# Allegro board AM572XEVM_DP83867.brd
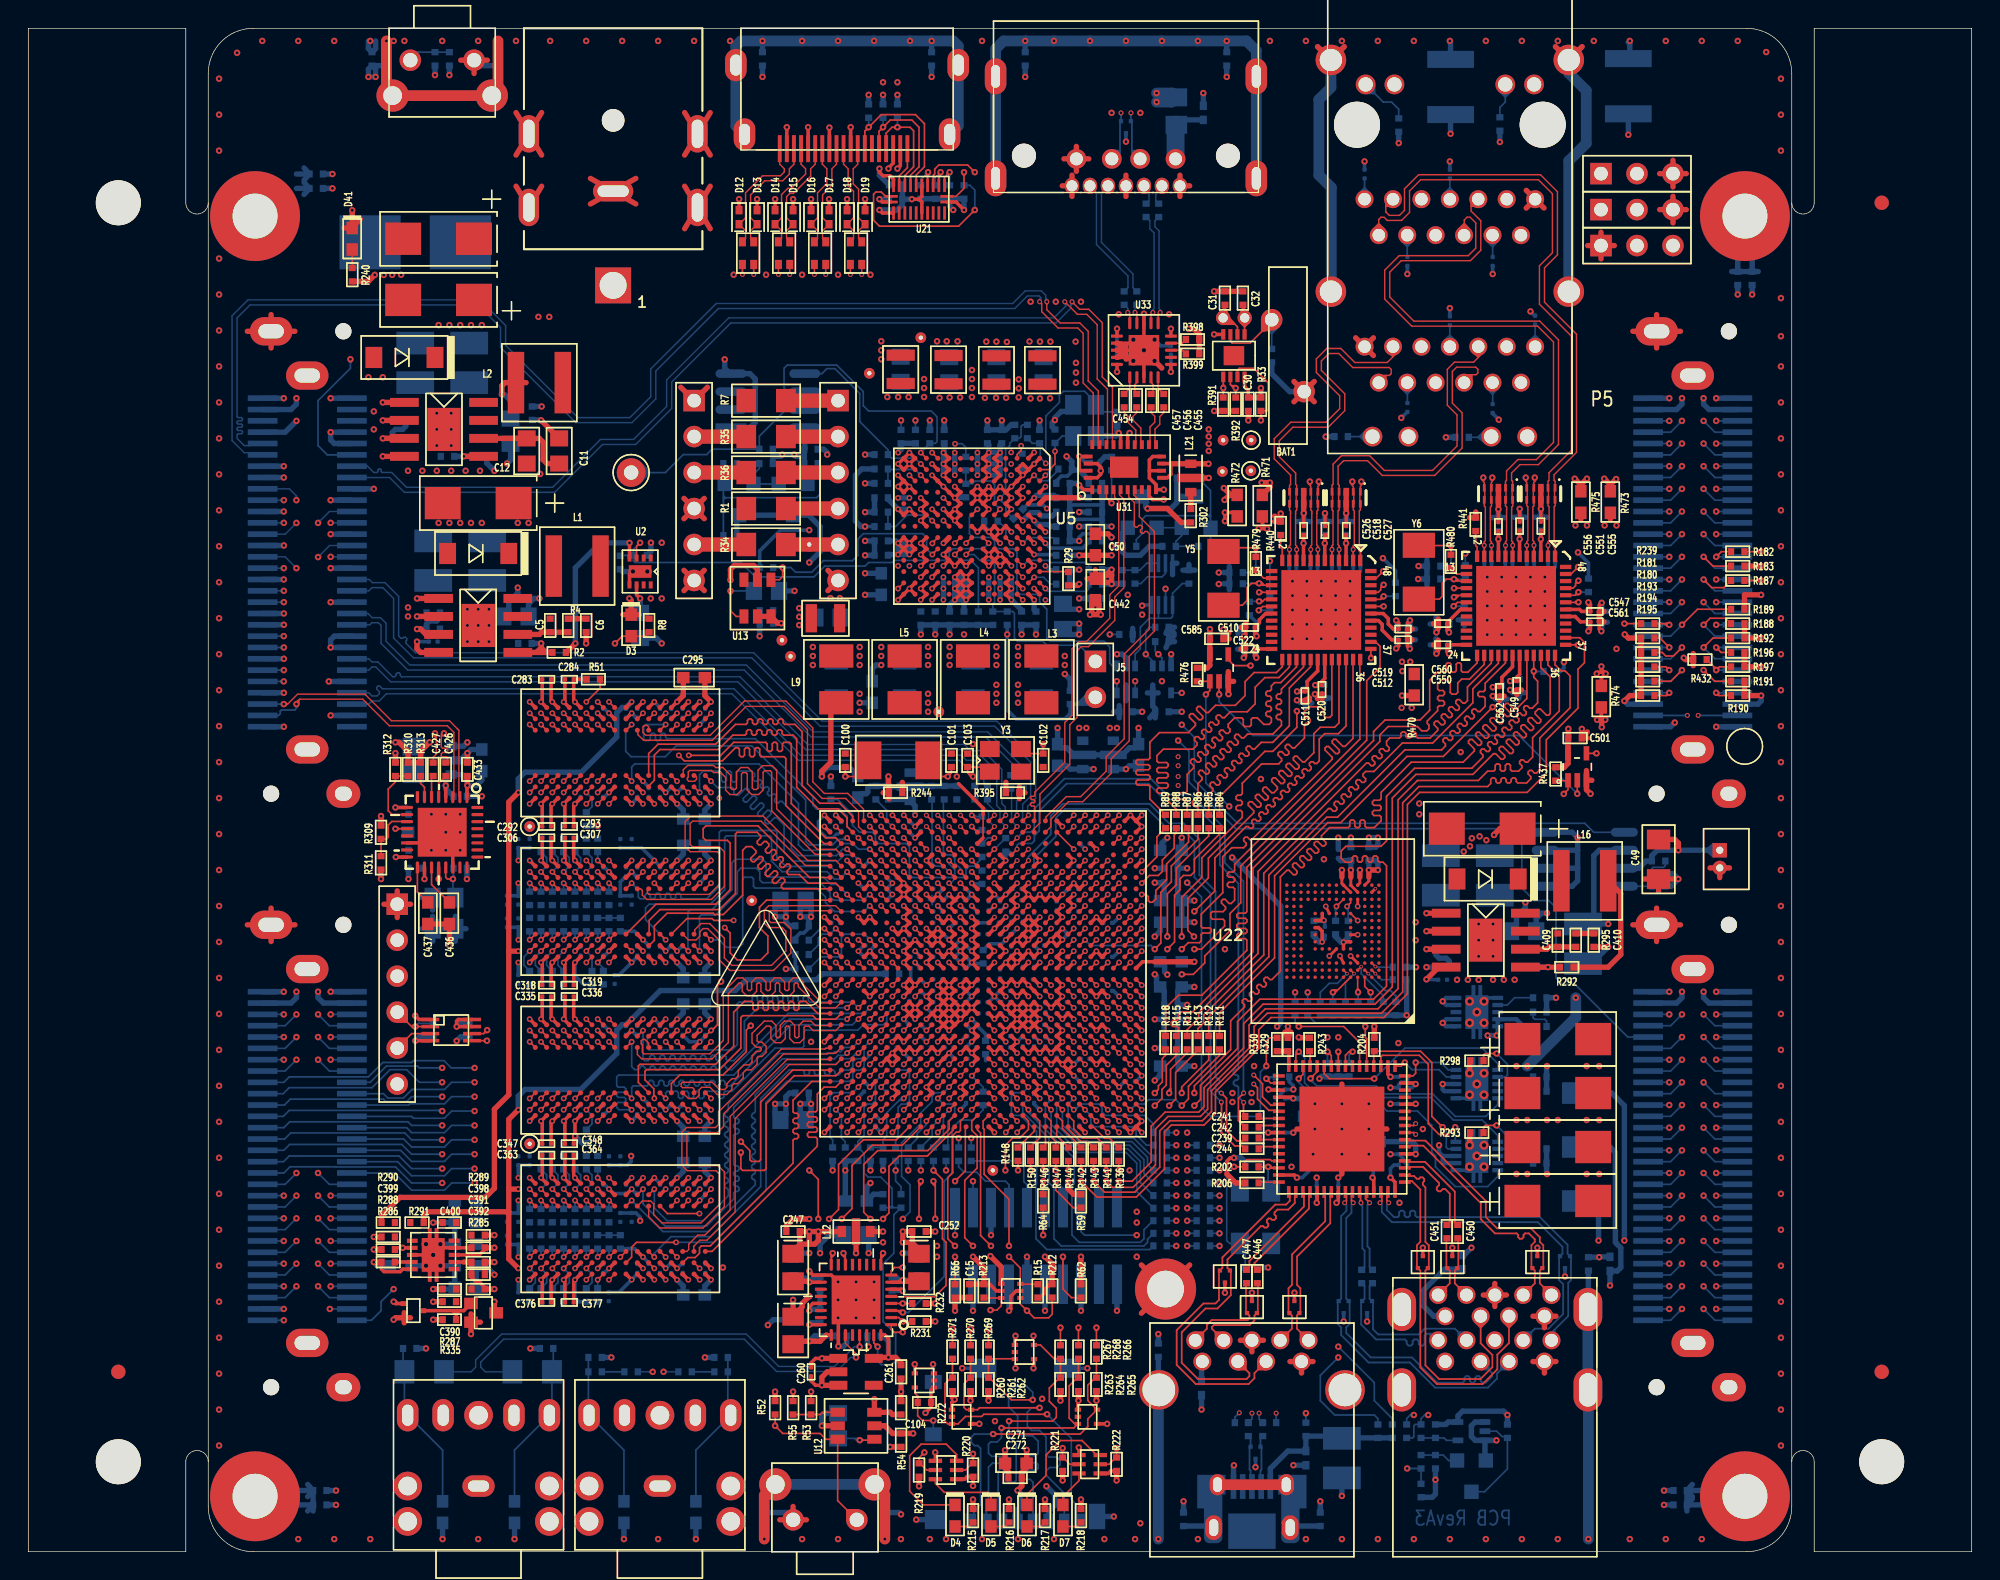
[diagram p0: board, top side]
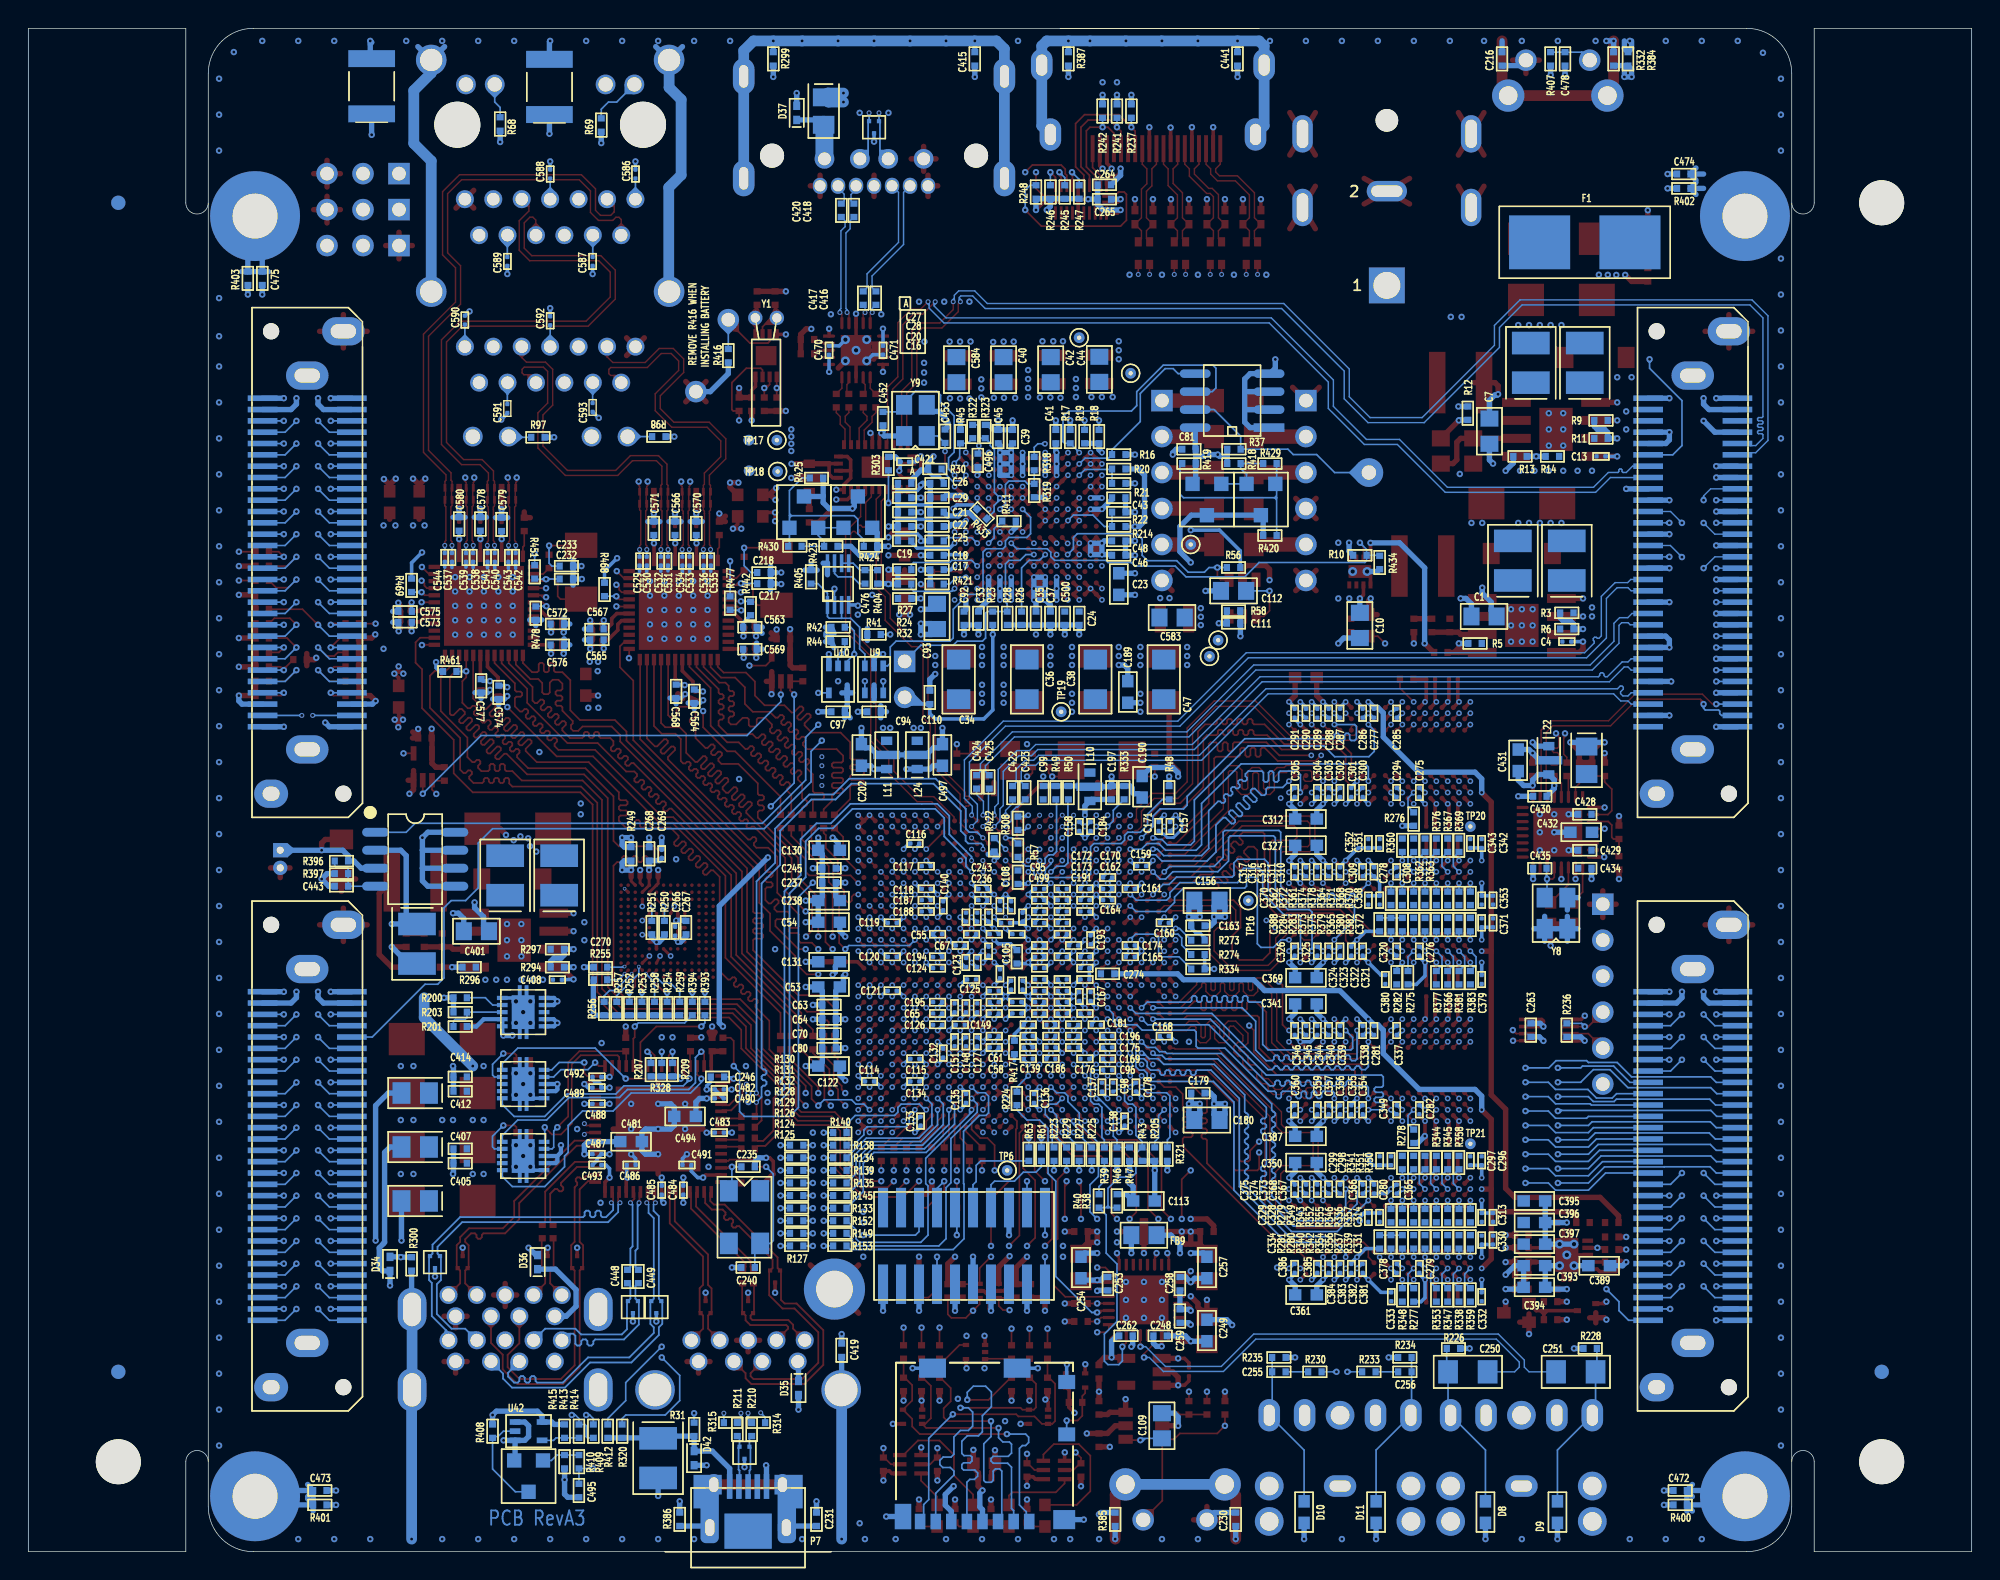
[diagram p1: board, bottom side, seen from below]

Outline 137.16 x 107.57 mm; copper layers: TOP, GND_L2, INT_L3, GND_L4, SIG_L5, PWR_L6, PWR_L7, SIG_L8, GND_L9, SIG_L10, GND_L11, BOTTOM. Coordinates in mm from the lower left corner of the outline.
Outline path: 12.7,6.35 arc(11.91,7.14) 11.11,6.35 11.11,0 0,0 0,107.57 11.11,107.57 11.11,95.25 arc(11.91,94.46) 12.7,95.25 ; 124.46,6.35 arc(125.25,7.14) 126.05,6.35 126.05,0 137.16,0 137.16,107.57 126.05,107.57 126.05,95.25 arc(125.25,94.46) 124.46,95.25 ; 12.7,104.39 12.7,3.17 arc(13.63,0.93) 15.88,0 121.28,0 arc(123.53,0.93) 124.46,3.17 124.46,104.39 arc(123.53,106.64) 121.28,107.57 15.88,107.57 arc(13.63,106.64) 12.7,104.39

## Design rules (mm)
net group AIC_MCLK: nets AIC_MCLK AIC_MCLKR
net group AUDIN: nets AUDIN_L AUDIN_R
net group AUDIO: nets AUDIO_L AUDIO_R
net group CON.PCIE_RX0: nets CON.PCIE_RXN0 CON.PCIE_RXP0
net group CON.PCIE_RX1: nets CON.PCIE_RXN1 CON.PCIE_RXP1
net group CON.PCIE_TXN0: nets CON.PCIE_TXN0 PCIE_TXN0
net group CON.PCIE_TXN1: nets CON.PCIE_TXN1 PCIE_TXN1
net group CON.PCIE_TXP0: nets CON.PCIE_TXP0 PCIE_TXP0
net group CON.PCIE_TXP1: nets CON.PCIE_TXP1 PCIE_TXP1
net group CONN_SATA_RXN: nets CONN_SATA_RXN ESATA_R-
net group CONN_SATA_RXP: nets CONN_SATA_RXP ESATA_R+
net group CONN_SATA_TXN: nets CONN_SATA_TXN ESATA_T-
net group CONN_SATA_TXP: nets CONN_SATA_TXP ESATA_T+
net group CPU_POR_RESETN: nets CPU_POR_RESETN TPS_RST
net group DDR1_DQS0: nets DDR1_DQS0 DDR1_DQSN0
net group DDR1_DQS2: nets DDR1_DQS2 DDR1_DQSN2
net group DDR2_DQS0: nets DDR2_DQS0 DDR2_DQSN0
net group DDR2_DQS2: nets DDR2_DQS2 DDR2_DQSN2
net group DIFFPAIR0: nets GPIO3_23 GPIO3_26
net group DIFFPAIR1: nets GPIO3_16 GPIO3_18
net group DIFFPAIR2: nets GPIO3_8 GPIO3_14
net group DIFFPAIR3: nets GPIO3_7 GPIO3_10
net group DIFFPAIR4: nets GPIO3_20 GPIO3_24
net group DIFFPAIR5: nets GPIO3_11 GPIO3_12
net group DIFFPAIR6: nets GPIO3_9 GPIO3_15
net group DIFFPAIR7: nets GPIO2_31 GPIO3_6
net group EMAC[0]_TXC: nets EMAC[0]_TXC R_EMAC[0]_TXC
net group EMAC[0]_TXCTL: nets EMAC[0]_TXCTL R_EMAC[0]_TXCTL
net group EMAC[0]_TXD0: nets EMAC[0]_TXD0 R_EMAC[0]_TXD0
net group EMAC[0]_TXD1: nets EMAC[0]_TXD1 R_EMAC[0]_TXD1
net group EMAC[0]_TXD2: nets EMAC[0]_TXD2 R_EMAC[0]_TXD2
net group EMAC[0]_TXD3: nets EMAC[0]_TXD3 R_EMAC[0]_TXD3
net group EMAC[1]_TXC: nets EMAC[1]_TXC R_EMAC[1]_TXC
net group EMAC[1]_TXCTL: nets EMAC[1]_TXCTL R_EMAC[1]_TXCTL
net group EMAC[1]_TXD0: nets EMAC[1]_TXD0 R_EMAC[1]_TXD0
net group EMAC[1]_TXD1: nets EMAC[1]_TXD1 R_EMAC[1]_TXD1
net group EMAC[1]_TXD2: nets EMAC[1]_TXD2 R_EMAC[1]_TXD2
net group EMAC[1]_TXD3: nets EMAC[1]_TXD3 R_EMAC[1]_TXD3
net group ETH0_TRD[0]: nets ETH0_TRD[0]N ETH0_TRD[0]P
net group ETH0_TRD[1]: nets ETH0_TRD[1]N ETH0_TRD[1]P
net group ETH0_TRD[2]: nets ETH0_TRD[2]N ETH0_TRD[2]P
net group ETH0_TRD[3]: nets ETH0_TRD[3]N ETH0_TRD[3]P
net group ETH1_TRD[0]: nets ETH1_TRD[0]N ETH1_TRD[0]P
net group ETH1_TRD[1]: nets ETH1_TRD[1]N ETH1_TRD[1]P
net group ETH1_TRD[2]: nets ETH1_TRD[2]N ETH1_TRD[2]P
net group ETH1_TRD[3]: nets ETH1_TRD[3]N ETH1_TRD[3]P
net group EXP_SATA_RX: nets EXP_SATA_RXN EXP_SATA_RXP
net group EXP_SATA_TX: nets EXP_SATA_TXN EXP_SATA_TXP
net group HDMI_TX0: nets HDMI_TX0+ HDMI_TX0-
net group HDMI_TX1: nets HDMI_TX1+ HDMI_TX1-
net group HDMI_TXC: nets HDMI_TXC+ HDMI_TXC-
net group PCI_CONN_REF: nets PCI_CONN_REFN PCI_CONN_REFP
net group PUSB_RXN0: nets PUSB_RXN0 USB_SSTXM0
net group PUSB_RXP0: nets PUSB_RXP0 USB_SSTXP0
net group PUSB_TXN0: nets PUSB_TXN0 USB_SSRXM0
net group PUSB_TXP0: nets PUSB_TXP0 USB_SSRXP0
net group RDRXN: nets RDRXN RXN_MUXC
net group RDRXP: nets RDRXP RXP_MUXC
net group RDTXN: nets RDTXN TXN_MUXC
net group RDTXP: nets RDTXP TXP_MUXC
net group RHDMI_TX0: nets RHDMI_TX0+ RHDMI_TX0-
net group RHDMI_TX1: nets RHDMI_TX1+ RHDMI_TX1-
net group RHDMI_TXC: nets RHDMI_TXC+ RHDMI_TXC-
net group RTCK: nets RTCK RTCKR
net group SAT_RX: nets SAT_RXN SAT_RXP
net group SATA_TX0: nets SAT_TXN SAT_TXP
net group SERDES_CLKN: nets SERDES_CLKN SERDES_IN_REFN
net group SERDES_CLKP: nets SERDES_CLKP SERDES_IN_REFP
net group TCK: nets TCK TCLK
net group TDO: nets TDO TDOR
net group TX1+: nets TX1+ USB_TXP1
net group TX1-: nets TX1- USB_TXM1
net group TX2+: nets TX2+ USB_TXP2
net group TX2-: nets TX2- USB_TXM2
net group TX+: nets TX+ USB_TXP0
net group TX-: nets TX- USB_TXM0
net group USB1_D: nets USB1_DM USB1_DP
net group USB2_D: nets USB2_DM USB2_DP
net group USB2_DEX: nets USB2_DMEX USB2_DPEX
net group USB_D0: nets USB_DM0 USB_DP0
net group USB_D1: nets USB_DM1 USB_DP1
net group USB_D2: nets USB_DM2 USB_DP2
net group USB_D3: nets USB_DM3 USB_DP3
net group USB_RX0: nets USB_RXM0 USB_RXP0
net group USB_RX1: nets USB_RXM1 USB_RXP1
net group USB_RX2: nets USB_RXM2 USB_RXP2
net group USBSP_D: nets USBSP_DM USBSP_DP
net group VBUS_DET: nets N29907779 VBUS_DET
net group VOUT1_CLK: nets VOUT1_CLK VOUT1_RDCLK
net group VOUT1_D0: nets VOUT1_D0 VOUT1_RD0
net group VOUT1_D1: nets VOUT1_D1 VOUT1_RD1
net group VOUT1_D2: nets VOUT1_D2 VOUT1_RD2
net group VOUT1_D3: nets VOUT1_D3 VOUT1_RD3
net group VOUT1_D4: nets VOUT1_D4 VOUT1_RD4
net group VOUT1_D5: nets VOUT1_D5 VOUT1_RD5
net group VOUT1_D6: nets VOUT1_D6 VOUT1_RD6
net group VOUT1_D7: nets VOUT1_D7 VOUT1_RD7
net group VOUT1_D8: nets VOUT1_D8 VOUT1_RD8
net group VOUT1_D9: nets VOUT1_D9 VOUT1_RD9
net group VOUT1_D10: nets VOUT1_D10 VOUT1_RD10
net group VOUT1_D11: nets VOUT1_D11 VOUT1_RD11
net group VOUT1_D12: nets VOUT1_D12 VOUT1_RD12
net group VOUT1_D13: nets VOUT1_D13 VOUT1_RD13
net group VOUT1_D14: nets VOUT1_D14 VOUT1_RD14
net group VOUT1_D15: nets VOUT1_D15 VOUT1_RD15
net group VOUT1_D16: nets VOUT1_D16 VOUT1_RD16
net group VOUT1_D17: nets VOUT1_D17 VOUT1_RD17
net group VOUT1_D18: nets VOUT1_D18 VOUT1_RD18
net group VOUT1_D19: nets VOUT1_D19 VOUT1_RD19
net group VOUT1_D20: nets VOUT1_D20 VOUT1_RD20
net group VOUT1_D21: nets VOUT1_D21 VOUT1_RD21
net group VOUT1_D22: nets VOUT1_D22 VOUT1_RD22
net group VOUT1_D23: nets VOUT1_D23 VOUT1_RD23
net group VOUT1_DE: nets VOUT1_DE VOUT1_RDE
net group VOUT1_HSYNC: nets VOUT1_HSYNC VOUT1_RHSYNC
net group VOUT1_RVSYNC: nets VOUT1_RVSYNC VOUT1_VSYNC
net group DDR1_DQ0: nets DDR1_D0 DDR1_D1 DDR1_D2 DDR1_D3 DDR1_D4 DDR1_D5 DDR1_D6 DDR1_D7 DDR1_DQM0
net group DDR1_DQ1: nets DDR1_D8 DDR1_D9 DDR1_D10 DDR1_D11 DDR1_D12 DDR1_D13 DDR1_D14 DDR1_D15 DDR1_DQM1 DDR1_DQS1 DDR1_DQSN1
net group DDR1_DQ2: nets DDR1_D16 DDR1_D17 DDR1_D18 DDR1_D19 DDR1_D20 DDR1_D21 DDR1_D22 DDR1_D23 DDR1_DQM2
net group DDR1_DQ3: nets DDR1_D24 DDR1_D25 DDR1_D26 DDR1_D27 DDR1_D28 DDR1_D29 DDR1_D30 DDR1_D31 DDR1_DQM3 DDR1_DQS3 DDR1_DQSN3
net group DDR2_DQ0: nets DDR2_D0 DDR2_D1 DDR2_D2 DDR2_D3 DDR2_D4 DDR2_D5 DDR2_D6 DDR2_D7 DDR2_DQM0
net group DDR2_DQ1: nets DDR2_D8 DDR2_D9 DDR2_D10 DDR2_D11 DDR2_D12 DDR2_D13 DDR2_D14 DDR2_D15 DDR2_DQM1 DDR2_DQS1 DDR2_DQSN1
net group DDR2_DQ2: nets DDR2_D16 DDR2_D17 DDR2_D18 DDR2_D19 DDR2_D20 DDR2_D21 DDR2_D22 DDR2_D23 DDR2_DQM2
net group DDR2_DQ3: nets DDR2_D24 DDR2_D25 DDR2_D26 DDR2_D27 DDR2_D28 DDR2_D29 DDR2_D30 DDR2_D31 DDR2_DQM3 DDR2_DQS3 DDR2_DQSN3
net group DDR_VREFSTL1: nets DDR_VREFSTL1 DDR_VREFSTL2 VTT_VOSNS
net group EMAC0_RX: nets EMAC[0]_RXC EMAC[0]_RXCTL EMAC[0]_RXD0 EMAC[0]_RXD1 EMAC[0]_RXD2 EMAC[0]_RXD3
net group EMAC1_RX: nets EMAC[1]_RXC EMAC[1]_RXCTL EMAC[1]_RXD0 EMAC[1]_RXD1 EMAC[1]_RXD2 EMAC[1]_RXD3
net group ENET_PORZ: nets ENET_PORZ PORZ RTC_ISO
net group HDMI: nets HDMI_TX2+ HDMI_TX2- RHDMI_TX2+ RHDMI_TX2-
net group VDAC_3V3: nets AIC_AVDD_DAC3.3 GND_SIGNAL VDAC_3V3
nets with their own width: min track width 0.254; nets ETH0_1V0 ETH0_2V5 ETH0_3V3 ETH1_1V0 ETH1_2V5 ETH1_3V3 LDO_VRTC

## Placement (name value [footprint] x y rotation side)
BAT1  CR1220MFR FV,DNI  [BATT2_78X492]  88.9 84.45 270 top
C1  0.1uf,25V,0805  [805]  34.42 66.04 180 bottom
C2  100uF,10V  [6032]  31.75 74.04 180 top
C3  4.7uF,50V.LESR  [1210]  28.58 69.98 90 bottom
C4  8.2nF,10V,0201  [201]  28.58 64.26 0 bottom
C5  22pF  [402]  36.83 65.41 270 top
C6  .001uF,50V  [402]  39.37 65.41 270 top
C7  0.1uf,25V,0805  [805]  34.04 79.12 270 bottom
C8  100uF,10V  [6032]  28.96 88.39 180 top
C9  100uF,10V  [6032]  28.96 92.71 180 top
C10  220pF,50V  [805]  43.18 65.41 270 bottom
C11  820pF,50V  [805]  37.47 77.72 90 top
C12  15pF,50V  [805]  35.18 77.72 270 top
C13  8.2nF,10V,0201  [201]  26.16 77.34 0 bottom
C14  4.7uF,50V.LESR  [1210]  27.3 83.95 90 bottom
C15  0.1uf,16V  [402]  66.42 18.41 270 top
C16  0.1uf,16V  [402]  75.31 72.39 180 bottom
C17  2.2uF,6.3V  [402]  73.03 69.34 180 bottom
C18  2.2uF,6.3V  [402]  73.03 70.36 180 bottom
C19  2.2uF,6.3V  [402]  75.31 71.37 180 bottom
C20  2.2uF,6.3V  [402]  75.31 73.41 180 bottom
C21  2.2uF,6.3V  [402]  73.03 73.41 180 bottom
C22  2.2uF,6.3V  [402]  73.03 72.39 180 bottom
C23  10uF,6.3V  [603]  60.2 68.33 90 bottom
C24  2.2uF,6.3V  [402]  62.99 65.91 90 bottom
C25  2.2uF,6.3V  [402]  73.03 71.37 180 bottom
C26  2.2uF,6.3V  [402]  73.03 75.44 180 bottom
C27  2.2uF,6.3V  [402]  75.31 75.44 180 bottom
C28  2.2uF,6.3V  [402]  75.31 74.42 180 bottom
C29  2.2uF,6.3V  [402]  73.03 74.42 180 bottom
C30  0.1uf,16V  [402]  86.11 81.03 270 top
C31  10pF,50V  [402]  84.45 88.52 90 top
C32  10pF,50V  [402]  85.72 88.52 90 top
C33  4.7uF,6.3V  [402]  70.1 65.91 270 bottom
C34  47uF,6.3V,1206  [1206]  71.5 61.59 90 bottom
C35  4.7uF,6.3V  [402]  66.04 65.91 270 bottom
C36  47uF,6.3V,1206  [1206]  66.68 61.59 90 bottom
C37  4.7uF,6.3V  [402]  65.02 65.91 270 bottom
C38  47uF,6.3V,1206  [1206]  61.85 61.59 90 bottom
C39  4.7uF,6.3V  [402]  67.69 78.74 90 bottom
C40  47uF,6.3V  [805]  68.33 83.46 270 bottom
C41  4.7uF,6.3V  [402]  64.64 78.74 90 bottom
C42  47uF,6.3V  [805]  65 83.46 270 bottom
C43  4.7uF,6.3V  [402]  60.2 74.42 180 bottom
C44  47uF,6.3V  [805]  61.57 83.49 270 bottom
C45  4.7uF,6.3V  [402]  68.71 78.74 90 bottom
C46  4.7uF,6.3V  [402]  60.2 70.36 180 bottom
C47  47uF,6.3V,1206  [1206]  57.02 61.59 90 bottom
C48  4.7uF,6.3V  [402]  60.2 71.37 180 bottom
C49  47uF,6.3V,1206  [1206]  115.06 48.9 270 top
C50  10uF,6.3V  [603]  75.31 71.12 270 top
C51  0.1uF/201  [201]  70.99 38.4 90 bottom
C52  0.22uF/201  [201]  68.99 38 0 bottom
C53  10uF,6.3V  [603]  80.65 39.88 0 bottom
C54  10uF,6.3V  [603]  80.65 44.45 0 bottom
C55  0.1uF/201  [201]  72.99 43.61 0 bottom
C56  0.22uF/201  [201]  65.79 42.81 180 bottom
C57  0.1uF/201  [201]  68.99 38.8 180 bottom
C58  0.1uF/201  [201]  68.99 35.6 180 bottom
C59  0.1uF/201  [201]  70.19 38.4 90 bottom
C60  0.1uF/201  [201]  70.19 41.61 270 bottom
C61  0.1uF/201  [201]  68.99 36.4 0 bottom
C62  0.1uF/201  [201]  64.19 42.01 180 bottom
C63  2.2uF,6.3V  [402]  80.65 38.61 0 bottom
C64  4.7uF,6.3V  [402]  80.65 37.59 0 bottom
C65  0.47uF/201  [201]  72.99 38 0 bottom
C66  0.1uF/201  [201]  65.79 42.01 180 bottom
C67  0.1uF/201  [201]  71.39 42.81 0 bottom
C68  0.1uF/201  [201]  64.19 43.61 0 bottom
C69  0.1uF/201  [201]  63.39 42.81 180 bottom
C70  4.7uF,6.3V  [402]  80.65 36.58 0 bottom
C71  0.1uF/201  [201]  64.99 36.4 180 bottom
C72  0.1uF/201  [201]  68.59 40.81 270 bottom
C73  0.1uF/201  [201]  70.99 44.81 90 bottom
C74  0.1uF/201  [201]  70.19 44.81 90 bottom
C75  0.1uF/201  [201]  69.39 42.41 270 bottom
C76  0.1uF/201  [201]  67.39 43.61 180 bottom
C77  0.1uF/201  [201]  64.19 39.6 180 bottom
C78  0.22uF/201  [201]  70.59 43.61 180 bottom
C79  0.47uF/201  [201]  68.19 44.41 180 bottom
C80  2.2uF,6.3V  [402]  80.65 35.56 0 bottom
C81  0.1uf,16V  [402]  55.25 77.85 0 bottom
C82  0.1uF/201  [201]  64.19 38.8 180 bottom
C83  0.1uF/201  [201]  64.19 38 180 bottom
C84  0.1uF/201  [201]  64.19 40.41 180 bottom
C85  0.1uF/201  [201]  67.39 38 0 bottom
C86  0.1uF/201  [201]  67.39 38.8 0 bottom
C87  0.1uF/201  [201]  65.79 40.41 0 bottom
C88  0.22uF/201  [201]  65.79 39.6 180 bottom
C89  0.22uF/201  [201]  64.99 37.2 180 bottom
C90  1uF,4V,0201  [201]  65.79 38 0 bottom
C91  1uF,4V,0201  [201]  65.79 38.8 0 bottom
C92  2.2uF,6.3V  [402]  71.12 65.91 90 bottom
C93  22uF,6.3V  [805]  73.03 66.04 270 bottom
C94  0.1uf,16V  [402]  77.47 59.31 0 bottom
C95  0.1uF/201  [201]  65.79 46.81 180 bottom
C96  0.1uF/201  [201]  60.99 34 0 bottom
C97  0.1uf,16V  [402]  80.01 59.31 0 bottom
C98  0.1uF/201  [201]  60.59 32.8 270 bottom
C99  0.1uf,16V  [402]  65.53 53.59 90 bottom
C100  18pF,50V  [402]  57.66 55.88 90 top
C101  18pF,50V  [402]  65.15 55.88 90 top
C102  12pF,50V  [402]  71.63 55.88 270 top
C103  12pF,50V  [402]  66.29 55.88 90 top
C104  0.1uf,16V  [402]  61.59 10.16 90 top
C105  0.1uf,16V  [402]  67.39 42.01 270 bottom
C108  0.1uf,16V  [402]  67.31 47.62 90 bottom
C109  220pF,50V  [805]  57.15 8.89 90 bottom
C110  0.1uf,16V  [402]  73.53 60.33 90 bottom
C111  0.1uf,16V  [402]  52.1 65.56 180 bottom
C112  220pF,50V  [805]  52.1 67.84 0 bottom
C113  10uF,6.3V  [603]  58.42 24.77 180 bottom
C114  0.1uF/201  [201]  77.79 33.2 0 bottom
C115  0.1uF/201  [201]  74.59 34.8 180 bottom
C116  0.1uF/201  [201]  74.59 50.01 180 bottom
C117  0.1uF/201  [201]  73.79 48.41 0 bottom
C118  0.1uF/201  [201]  73.79 46.81 180 bottom
C119  0.1uF/201  [201]  76.19 44.41 0 bottom
C120  0.1uF/201  [201]  76.19 42.01 0 bottom
C121  0.1uF/201  [201]  76.19 39.6 0 bottom
C122  10uF,6.3V  [603]  80.65 34.29 0 bottom
C123  0.1uF/201  [201]  70.99 41.61 90 bottom
C124  0.1uF/201  [201]  72.99 41.21 180 bottom
C125  0.1uF/201  [201]  70.59 40.41 180 bottom
C126  0.1uF/201  [201]  72.99 37.2 0 bottom
C127  0.1uF/201  [201]  70.19 36 90 bottom
C128  0.1uF/201  [201]  66.59 35.6 180 bottom
C129  0.1uF/201  [201]  64.99 35.6 0 bottom
C130  10uF,6.3V  [603]  80.65 49.53 0 bottom
C131  10uF,6.3V  [603]  80.65 41.66 0 bottom
C132  0.1uF/201  [201]  72.59 35.2 270 bottom
C133  0.1uF/201  [201]  74.19 30.4 270 bottom
C134  0.1uF/201  [201]  74.59 33.2 180 bottom
C135  0.1uF/201  [201]  70.99 32 270 bottom
C136  0.1uF/201  [201]  66.19 32 270 bottom
C137  0.1uF/201  [201]  61.39 32.8 90 bottom
C138  0.1uF/201  [201]  59.79 30.4 270 bottom
C139  0.1uF/201  [201]  66.59 34.8 180 bottom
C140  0.1uF/201  [201]  72.59 45.61 90 bottom
C141  1uF,4V,0201  [201]  66.99 44.81 90 bottom
C142  1uF,4V,0201  [201]  62.59 41.21 180 bottom
C143  1uF,4V,0201  [201]  63.39 36.4 180 bottom
C144  1uF,4V,0201  [201]  67.79 45.61 90 bottom
C145  1uF,4V,0201  [201]  62.59 40.41 0 bottom
C146  1uF,4V,0201  [201]  66.59 36.4 0 bottom
C147  1uF,4V,0201  [201]  65.79 45.21 0 bottom
C148  1uF,4V,0201  [201]  70.99 36 270 bottom
C149  1uF,4V,0201  [201]  71.39 37.2 0 bottom
C150  1uF,4V,0201  [201]  62.59 42.01 180 bottom
C151  1uF,4V,0201  [201]  71.79 36 90 bottom
C152  1uF,4V,0201  [201]  68.59 45.61 90 bottom
C153  1uF,4V,0201  [201]  63.39 37.2 180 bottom
C154  1uF,4V,0201  [201]  66.59 37.2 180 bottom
C155  1uF,4V,0201  [201]  71.79 38.4 270 bottom
C156  22uF,6.3V  [805]  53.98 45.97 180 bottom
C157  0.1uF/201  [201]  56.58 51.21 90 bottom
C158  0.1uF/201  [201]  62.99 51.21 90 bottom
C159  0.1uF/201  [201]  58.59 48.41 0 bottom
C160  0.1uF/201  [201]  56.98 44.41 180 bottom
C161  0.22uF/201  [201]  59.39 46.81 180 bottom
C162  0.22uF/201  [201]  60.99 46.81 180 bottom
C163  4.7uF,6.3V  [402]  54.61 44.2 180 bottom
C164  1uF,4V,0201  [201]  60.99 46.01 180 bottom
C165  0.22uF/201  [201]  59.39 42.01 180 bottom
C166  0.22uF/201  [201]  62.99 39.2 90 bottom
C167  0.22uF/201  [201]  62.19 39.2 90 bottom
C168  0.22uF/201  [201]  56.98 36.4 180 bottom
C169  0.1uF/201  [201]  60.99 34.8 180 bottom
C170  0.1uF/201  [201]  60.99 47.61 180 bottom
C171  0.22uF/201  [201]  57.38 51.21 270 bottom
C172  0.22uF/201  [201]  62.59 46.81 0 bottom
C173  0.1uF/201  [201]  62.59 46.01 0 bottom
C174  0.1uF/201  [201]  59.39 42.81 180 bottom
C175  0.1uF/201  [201]  60.99 35.6 180 bottom
C176  0.1uF/201  [201]  62.59 34.8 0 bottom
C177  0.1uF/201  [201]  63.39 35.6 0 bottom
C178  0.1uF/201  [201]  58.99 32.8 270 bottom
C179  4.7uF,6.3V  [402]  54.61 32.38 180 bottom
C180  22uF,6.3V  [805]  53.98 30.48 180 bottom
C181  0.1uF/201  [201]  61.79 37.2 180 bottom
C182  0.1uF/201  [201]  65.79 44.41 180 bottom
C183  0.1uF/201  [201]  62.59 38 180 bottom
C184  0.1uF/201  [201]  62.19 51.21 90 bottom
C185  0.1uF/201  [201]  64.19 46.81 180 bottom
C186  0.1uF/201  [201]  64.99 34.8 180 bottom
C187  0.1uF/201  [201]  73.79 46.01 0 bottom
C188  0.1uF/201  [201]  73.79 45.21 0 bottom
C189  10uF,6.3V  [603]  59.56 60.71 90 bottom
C190  10uF,6.3V  [603]  58.55 54.01 270 bottom
C191  0.1uF/201  [201]  62.59 45.21 0 bottom
C192  0.1uF/201  [201]  64.19 44.41 180 bottom
C193  0.1uF/201  [201]  62.19 43.21 270 bottom
C194  0.1uF/201  [201]  72.99 42.01 0 bottom
C195  0.1uF/201  [201]  72.99 38.8 0 bottom
C196  0.1uF/201  [201]  60.99 36.4 180 bottom
C197  .001uf,50V  [402]  60.71 53.59 90 bottom
C198  0.1uF/201  [201]  65.79 41.21 0 bottom
C199  0.1uF/201  [201]  67.79 40.01 270 bottom
C200  0.1uF/201  [201]  68.99 39.6 180 bottom
C201  0.1uF/201  [201]  68.99 43.61 0 bottom
C202  10uF,6.3V  [603]  78.36 56.26 90 bottom
C203  0.1uF/201  [201]  66.99 40.01 270 bottom
C204  0.1uF/201  [201]  69.39 44.81 90 bottom
C215  10nF,2kV,1812  [1812]  112.93 103.48 90 bottom
C216  0.1uf,16V  [402]  33.15 105.41 90 bottom
C217  18pF,50V  [402]  85.24 68.35 0 bottom
C218  18pF,50V  [402]  85.24 69.14 0 bottom
C230  0.1uf,16V  [402]  51.94 2.29 270 bottom
C231  0.1uf,16V  [402]  81.53 2.29 270 bottom
C232  DNI  [402]  99.19 68.68 0 bottom
C233  DNI  [402]  99.19 69.6 0 bottom
C235  18pF,50V  [402]  86.36 27.18 180 bottom
C236  0.1uF/201  [201]  69.79 46.01 0 bottom
C237  .001uf,50V  [402]  80.65 47.24 0 bottom
C238  10uF,6.3V  [603]  80.65 45.97 0 bottom
C239  0.1uf,16V  [402]  86.36 29.21 0 top
C240  18pF,50V  [402]  86.36 20.07 0 bottom
C241  0.1uf,16V  [402]  86.36 30.73 0 top
C242  0.1uf,16V  [402]  86.36 29.97 0 top
C243  0.1uF/201  [201]  69.79 46.81 0 bottom
C244  0.1uf,16V  [402]  86.36 28.45 0 top
C245  .001uf,50V  [402]  80.65 48.26 0 bottom
C246  2.2uF,6.3V  [402]  88.52 33.53 0 bottom
C247  0.1uf,16V  [402]  53.98 22.61 180 top
C248  0.1uf,16V  [402]  57.28 15.24 0 bottom
C249  10uF,6.3V  [603]  53.98 15.62 90 bottom
C250  47uF,6.3V,1206  [1206]  35.56 12.7 0 bottom
C251  47uF,6.3V,1206  [1206]  27.94 12.7 180 bottom
C252  0.1uf,16V  [402]  62.87 22.61 0 top
C253  0.1uf,16V  [402]  60.96 18.92 270 bottom
C254  10uF,6.3V  [603]  62.87 20.07 90 bottom
C255  2.2uF,6.3V  [402]  48.89 12.7 0 bottom
C256  2.2uF,6.3V  [402]  40.01 12.7 180 bottom
C257  10uF,6.3V  [603]  53.98 20.07 90 bottom
C258  0.1uf,16V  [402]  55.88 18.92 270 bottom
C259  0.1uf,16V  [402]  55.88 16.64 90 bottom
C260  1uF,4V,0201  [201]  55.25 12.7 270 top
C261  4.7uF,6.3V  [402]  61.59 12.7 270 top
C262  0.1uf,16V  [402]  59.69 15.24 180 bottom
C263  0.1uf,16V  [402]  31.12 36.83 90 bottom
C264  0.1uf,16V  [402]  61.21 96.52 0 bottom
C265  4.7uF,6.3V  [402]  61.21 95.5 0 bottom
C266  0.22uF/201  [201]  91.5 43.81 270 bottom
C267  2.2uF,6.3V  [402]  90.74 44.07 90 bottom
C268  4.7uF,6.3V  [402]  93.34 49.28 90 bottom
C269  0.22uF/201  [201]  92.46 49.28 90 bottom
C270  0.1uf,16V  [402]  96.77 41.27 180 bottom
C271  10uF,6.3V  [603]  69.7 6.25 180 top
C272  0.1uf,16V  [402]  69.65 5.21 0 top
C273  0.1uF/201  [201]  64.19 45.21 180 bottom
C274  0.1uf,16V  [402]  60.99 40.81 180 bottom
C275  0.22uF/201  [201]  38.98 53.61 270 bottom
C276  0.22uF/201  [201]  38.98 42.41 270 bottom
C277  0.22uF/201  [201]  42.18 59.21 270 bottom
C278  0.22uF/201  [201]  42.18 48.01 270 bottom
C279  0.22uF/201  [201]  38.98 20 270 bottom
C280  0.22uF/201  [201]  42.18 25.6 270 bottom
C281  0.22uF/201  [201]  42.18 36.8 270 bottom
C282  0.22uF/201  [201]  38.98 31.2 270 bottom
C283  0.22uF/201  [201]  36.58 61.61 0 top
C284  0.22uF/201  [201]  38.18 61.61 0 top
C285  0.22uF/201  [201]  40.58 59.21 90 bottom
C286  0.22uF/201  [201]  42.98 59.21 90 bottom
C287  0.22uF/201  [201]  44.58 59.21 270 bottom
C288  0.22uF/201  [201]  45.38 59.21 90 bottom
C289  0.22uF/201  [201]  46.18 59.21 270 bottom
C290  0.22uF/201  [201]  46.98 59.21 270 bottom
C291  0.22uF/201  [201]  47.78 59.21 270 bottom
C292  0.22uF/201  [201]  36.58 51.21 0 top
C293  0.22uF/201  [201]  38.18 51.21 0 top
C294  0.22uF/201  [201]  40.58 53.61 270 bottom
C295  10uF,6.3V  [603]  46.99 61.72 180 top
C296  0.22uF/201  [201]  34.58 27.6 270 bottom
C297  0.22uF/201  [201]  35.38 27.6 270 bottom
C298  0.22uF/201  [201]  40.98 27.6 270 bottom
C299  0.22uF/201  [201]  41.78 27.6 270 bottom
C300  0.22uF/201  [201]  42.98 53.61 90 bottom
C301  0.22uF/201  [201]  43.78 53.61 270 bottom
C302  0.22uF/201  [201]  44.58 53.61 90 bottom
C303  0.22uF/201  [201]  45.38 53.61 90 bottom
C304  0.22uF/201  [201]  46.18 53.61 90 bottom
C305  0.22uF/201  [201]  47.78 53.61 270 bottom
C306  0.22uF/201  [201]  36.58 50.41 0 top
C307  0.22uF/201  [201]  38.18 50.41 0 top
C308  0.22uF/201  [201]  40.58 48.01 90 bottom
C309  0.22uF/201  [201]  42.98 48.01 90 bottom
C310  0.22uF/201  [201]  44.58 48.01 270 bottom
C311  0.22uF/201  [201]  45.38 48.01 90 bottom
C312  10uF,6.3V  [603]  46.98 51.73 0 bottom
C313  0.22uF/201  [201]  33.78 23.6 90 bottom
C314  0.22uF/201  [201]  34.58 23.6 90 bottom
C315  0.22uF/201  [201]  46.18 48.01 270 bottom
C316  0.22uF/201  [201]  46.98 48.01 90 bottom
C317  0.22uF/201  [201]  47.78 48.01 90 bottom
C318  0.22uF/201  [201]  36.58 40.01 180 top
C319  0.22uF/201  [201]  38.18 40.01 0 top
C320  0.22uF/201  [201]  40.58 42.41 270 bottom
C321  0.22uF/201  [201]  42.98 42.41 90 bottom
C322  0.22uF/201  [201]  43.78 42.41 270 bottom
C323  0.22uF/201  [201]  44.58 42.41 90 bottom
C324  0.22uF/201  [201]  45.38 42.41 90 bottom
C325  0.22uF/201  [201]  46.18 42.41 90 bottom
C326  0.22uF/201  [201]  47.78 42.41 270 bottom
C327  10uF,6.3V  [603]  46.98 49.88 180 bottom
C328  0.22uF/201  [201]  41.78 23.6 90 bottom
C329  0.22uF/201  [201]  42.58 23.6 90 bottom
C330  0.22uF/201  [201]  33.78 22 270 bottom
C331  0.22uF/201  [201]  34.58 22 270 bottom
C332  0.22uF/201  [201]  34.58 18 90 bottom
C333  0.22uF/201  [201]  40.96 18 90 bottom
C334  0.1uf,16V  [402]  41.78 21.88 90 bottom
C335  0.22uF/201  [201]  36.58 39.2 0 top
C336  0.22uF/201  [201]  38.18 39.2 0 top
C337  0.22uF/201  [201]  40.58 36.8 90 bottom
C338  0.22uF/201  [201]  42.98 36.8 90 bottom
C339  0.22uF/201  [201]  44.58 36.8 270 bottom
C340  0.22uF/201  [201]  45.38 36.8 90 bottom
C341  10uF,6.3V  [603]  46.98 38.68 180 bottom
C342  0.22uF/201  [201]  34.58 50.01 270 bottom
C343  0.22uF/201  [201]  35.38 50.01 270 bottom
C344  0.22uF/201  [201]  46.18 36.8 270 bottom
C345  0.22uF/201  [201]  46.98 36.8 90 bottom
C346  0.22uF/201  [201]  47.78 36.8 270 bottom
C347  0.22uF/201  [201]  36.58 28.8 0 top
C348  0.22uF/201  [201]  38.18 28.8 0 top
C349  0.22uF/201  [201]  40.58 31.2 270 bottom
C350  10uF,6.3V  [603]  46.98 27.48 180 bottom
C351  0.22uF/201  [201]  41.78 50.01 270 bottom
C352  0.22uF/201  [201]  42.58 50.01 270 bottom
C353  0.22uF/201  [201]  33.78 46.01 90 bottom
C354  0.22uF/201  [201]  42.98 31.2 90 bottom
C355  0.22uF/201  [201]  43.78 31.2 270 bottom
C356  0.22uF/201  [201]  44.58 31.2 90 bottom
C357  0.22uF/201  [201]  45.38 31.2 90 bottom
C358  0.22uF/201  [201]  34.58 46.01 90 bottom
C359  0.22uF/201  [201]  46.18 31.2 90 bottom
C360  0.22uF/201  [201]  47.78 31.2 270 bottom
C361  10uF,6.3V  [603]  46.98 18.13 0 bottom
C362  0.22uF/201  [201]  41.78 46.01 90 bottom
C363  0.22uF/201  [201]  36.58 28 0 top
C364  0.22uF/201  [201]  38.18 28 0 top
C365  0.22uF/201  [201]  40.58 25.6 90 bottom
C366  0.22uF/201  [201]  42.98 25.6 90 bottom
C367  0.22uF/201  [201]  44.58 25.6 270 bottom
C368  0.22uF/201  [201]  45.38 25.6 90 bottom
C369  10uF,6.3V  [603]  46.98 40.53 0 bottom
C370  0.22uF/201  [201]  42.58 46.01 90 bottom
C371  0.22uF/201  [201]  33.78 44.41 270 bottom
C372  0.22uF/201  [201]  34.58 44.41 270 bottom
C373  0.22uF/201  [201]  46.18 25.6 270 bottom
C374  0.22uF/201  [201]  46.98 25.6 90 bottom
C375  0.22uF/201  [201]  47.78 25.6 270 bottom
C376  0.22uF/201  [201]  36.58 17.6 0 top
C377  0.22uF/201  [201]  38.18 17.6 0 top
C378  0.22uF/201  [201]  40.58 20 270 bottom
C379  0.22uF/201  [201]  34.58 40.41 90 bottom
C380  0.22uF/201  [201]  41.38 40.41 90 bottom
C381  0.22uF/201  [201]  42.98 20 90 bottom
C382  0.22uF/201  [201]  43.78 20 270 bottom
C383  0.22uF/201  [201]  44.58 20 90 bottom
C384  0.22uF/201  [201]  45.38 20 90 bottom
C385  0.22uF/201  [201]  46.18 20 90 bottom
C386  0.22uF/201  [201]  47.78 20 270 bottom
C387  10uF,6.3V  [603]  46.98 29.33 0 bottom
C388  0.1uf,16V  [402]  41.78 44.28 90 bottom
C389  10uF,6.3V  [603]  26.29 20.19 0 bottom
C390  .001uf,50V  [402]  29.72 18.54 180 top
C391  .001uf,50V  [402]  31.75 20.45 0 top
C392  0.1uf,16V  [402]  31.75 19.56 0 top
C393  10uF,6.3V  [603]  30.86 20.19 180 bottom
C394  10uF,6.3V  [603]  30.86 18.67 180 bottom
C395  10uF,6.3V  [603]  30.86 24.77 180 bottom
C396  10uF,6.3V  [603]  30.86 23.24 180 bottom
C397  10uF,6.3V  [603]  30.86 21.72 180 bottom
C398  0.1uf,16V  [402]  31.75 21.46 180 top
C399  0.1uf,16V  [402]  25.4 22.23 180 top
C400  10pF,NPO  [402]  29.72 23.24 180 top
C401  0.1uf,25V,0805  [805]  105.54 43.81 180 bottom
C402  4.7uF,50V.LESR  [1210]  99.7 47.75 90 bottom
C403  100uF,10V  [6032]  102.62 51.05 180 top
C404  100uF,10V  [6032]  107.95 24.77 0 top
C405  0.1uf,16V  [402]  106.68 27.43 0 bottom
C406  100uF,10V  [6032]  107.95 28.57 0 top
C407  0.1uf,16V  [402]  106.68 28.45 0 bottom
C408  8.2nF,10V,0201  [201]  99.82 40.39 0 bottom
C409  22pF  [402]  107.95 43.18 270 top
C410  .001uF,50V  [402]  110.49 43.18 270 top
C411  100uF,10V  [6032]  107.95 32.38 0 top
C412  0.1uf,16V  [402]  106.68 32.51 0 bottom
C413  100uF,10V  [6032]  107.95 36.2 0 top
C414  0.1uf,16V  [402]  106.68 33.53 0 bottom
C415  0.1uf,16V  [402]  70.36 105.41 90 bottom
C416  0.01uf,16V  [402]  77.34 88.52 90 bottom
C417  0.01uf,16V  [402]  78.23 88.52 270 bottom
C418  0.01uf,16V  [402]  78.89 94.72 270 bottom
C419  0.1uf,16V  [402]  79.76 14.22 90 bottom
C420  0.01uf,16V  [402]  79.78 94.72 270 bottom
C421  0.1uF/201  [201]  75.31 76.96 180 bottom
C422  0.1uf,16V  [402]  67.69 53.59 90 bottom
C423  0.1uf,16V  [402]  66.8 53.59 90 bottom
C424  0.1uf,16V  [402]  70.23 54.36 90 bottom
C425  0.1uf,16V  [402]  69.34 54.36 90 bottom
C426  0.1uf,16V  [402]  29.46 55.24 90 top
C427  0.1uf,16V  [402]  28.58 55.24 90 top
C428  0.1uf,16V  [402]  27.3 52.07 0 bottom
C429  .001uf,50V  [402]  27.3 49.53 0 bottom
C430  0.1uf,16V  [402]  30.48 53.34 0 bottom
C431  10uF,6.3V  [603]  32 55.88 90 bottom
C432  10uF,6.3V  [603]  27.56 50.8 0 bottom
C433  0.1uf,16V  [402]  30.99 55.24 90 top
C434  0.1uf,16V  [402]  27.3 48.26 180 bottom
C435  CAP,DNI,0402  [402]  30.48 48.26 0 bottom
C436  10uF,6.3V  [603]  29.72 45.09 270 top
C437  10uF,6.3V  [603]  28.19 45.09 270 top
C438  4.7uF,50V.LESR  [1210]  31.12 83.95 90 bottom
C439  4.7uF,50V.LESR  [1210]  32.39 69.98 90 bottom
C440  4.7uF,50V.LESR  [1210]  103.5 47.75 90 bottom
C441  0.1uf,16V  [402]  51.82 105.41 90 bottom
C442  10uF,6.3V  [603]  75.31 67.94 90 top
C443  470pF,6.3V  [402]  115.06 46.99 0 bottom
C445  4.7uF,50V.LESR  [1210]  109.73 42.93 270 bottom
C446  0.1uf,16V  [402]  86.74 19.43 270 top
C447  0.1uf,16V  [402]  85.98 19.43 270 top
C448  0.1uf,16V  [402]  94.87 19.43 270 bottom
C449  0.1uf,16V  [402]  94.11 19.43 270 bottom
C450  0.1uf,16V  [402]  100.89 22.61 270 top
C451  0.1uf,16V  [402]  100.12 22.61 270 top
C452  16pF/0402/50V  [402]  76.84 80.01 270 bottom
C453  16pF/0402/50V  [402]  72.46 78.77 90 bottom
C454  0.01uf,16V  [402]  77.34 81.28 270 top
C455  0.01uf,16V  [402]  80.14 81.28 90 top
C456  0.01uf,16V  [402]  79.25 81.28 90 top
C457  0.01uf,16V  [402]  78.23 81.28 90 top
C470  0.1uF/201  [201]  80.65 84.84 90 bottom
C471  1uF,4V,0201  [201]  76.84 84.84 270 bottom
C472  0.1uf,16V  [402]  20.57 4.32 180 bottom
C473  0.1uf,16V  [402]  116.59 4.32 0 bottom
C474  0.1uf,16V  [402]  20.32 97.28 180 bottom
C475  0.1uf,16V  [402]  120.65 89.92 90 bottom
C476  0.33uf,16V  [402]  78.11 68.83 90 bottom
C478  0.1uf,16V  [402]  28.7 105.41 270 bottom
C479  1uF,50V  [1210]  92.71 6.6 270 bottom
C481  10uF,6.3V  [603]  94.61 28.96 180 bottom
C482  0.1uF/201  [201]  88.39 32.64 0 bottom
C483  0.1uF/201  [201]  88.39 29.59 0 bottom
C484  0.1uF/201  [201]  90.93 25.53 90 bottom
C485  0.1uF/201  [201]  92.46 25.53 90 bottom
C486  0.1uF/201  [201]  94.61 27.3 180 bottom
C487  0.1uF/201  [201]  97.03 28.07 180 bottom
C488  0.1uF/201  [201]  97.03 31.62 180 bottom
C489  0.1uF/201  [201]  97.03 32.77 180 bottom
C490  0.1uF/201  [201]  88.39 32 180 bottom
C491  0.1uF/201  [201]  90.68 27.3 0 bottom
C492  0.1uF/201  [201]  97.03 33.53 0 bottom
C493  0.1uF/201  [201]  97.03 27.3 0 bottom
C494  10uF,6.3V  [603]  90.81 30.73 0 bottom
C495  1uF,30V,0402  [402]  98.3 4.32 270 bottom
C496  2.2uF,6.3V  [402]  70.14 77.06 270 bottom
C497  10uF,6.3V  [603]  72.64 56.26 90 bottom
C498  0.1uF/201  [201]  64.19 46.01 180 bottom
C499  0.1uF/201  [201]  65.79 46.01 0 bottom
C500  2.2uF,6.3V  [402]  64.01 65.91 90 bottom
C501  0.01uF  [402]  109.17 57.45 0 top
C510  0.1uf,16V  [201]  86.24 65.26 180 top
C511  0.1uf,16V  [201]  90.1 60.43 270 top
C512  0.1uf,16V  [201]  97.03 64.39 0 top
C518  0.1uf,16V  [201]  91.52 72.11 90 top
C519  0.1uf,16V  [201]  97.03 65.15 0 top
C520  0.1uf,16V  [201]  91.31 60.88 270 top
C522  0.1uf,16V  [201]  86.22 63.74 180 top
C526  0.1uf,16V  [201]  90.02 72.11 90 top
C527  0.1uf,16V  [201]  93.01 72.11 90 top
C529  4.7pF/0201  [201]  94.02 69.95 90 bottom
C530  4.7pF/0201  [201]  93.51 69.95 90 bottom
C531  4.7pF/0201  [201]  92.02 69.95 90 bottom
C532  4.7pF/0201  [201]  92.52 69.95 90 bottom
C533  4.7pF/0201  [201]  90.49 69.95 90 bottom
C534  4.7pF/0201  [201]  91 69.95 90 bottom
C535  4.7pF/0201  [201]  88.99 69.95 90 bottom
C536  4.7pF/0201  [201]  89.5 69.95 90 bottom
C537  4.7pF/0201  [201]  107.26 70.21 90 bottom
C538  4.7pF/0201  [201]  105.77 70.21 90 bottom
C539  4.7pF/0201  [201]  106.27 70.21 90 bottom
C540  4.7pF/0201  [201]  104.24 70.21 90 bottom
C541  4.7pF/0201  [201]  104.75 70.21 90 bottom
C542  4.7pF/0201  [201]  102.77 70.21 90 bottom
C543  4.7pF/0201  [201]  103.28 70.21 90 bottom
C544  4.7pF/0201  [201]  107.77 70.21 90 bottom
C547  0.1uf,16V  [201]  110.57 66.4 0 top
C549  0.1uf,16V  [201]  105.05 61.16 270 top
C550  0.1uf,16V  [201]  99.82 64.03 180 top
C551  0.1uf,16V  [201]  105.26 72.42 90 top
C555  0.1uf,16V  [201]  106.76 72.42 90 top
C556  0.1uf,16V  [201]  103.76 72.39 90 top
C560  0.1uf,16V  [201]  99.82 65.53 180 top
C561  0.1uf,16V  [201]  110.57 65.66 0 top
C562  0.1uf,16V  [201]  103.84 60.73 270 top
C563  1uf,16V  [402]  86.23 65.28 180 bottom
C564  1uf,16V  [402]  90.16 60.41 270 bottom
C565  1uf,16V  [402]  97.03 64.39 0 bottom
C566  1uf,16V  [402]  91.52 72.26 90 bottom
C567  1uf,16V  [402]  97.03 65.15 0 bottom
C568  1uf,16V  [402]  91.44 60.75 270 bottom
C569  1uf,16V  [402]  86.23 63.73 180 bottom
C570  1uf,16V  [402]  90.02 72.26 90 bottom
C571  1uf,16V  [402]  93.01 72.26 90 bottom
C572  1uf,16V  [402]  99.82 65.51 180 bottom
C573  1uf,16V  [402]  110.57 65.63 0 bottom
C574  1uf,16V  [402]  103.96 60.68 270 bottom
C575  1uf,16V  [402]  110.57 66.4 0 bottom
C576  1uf,16V  [402]  99.82 64.03 180 bottom
C577  1uf,16V  [402]  105.21 61.14 270 bottom
C578  1uf,16V  [402]  105.26 72.57 90 bottom
C579  1uf,16V  [402]  103.76 72.54 90 bottom
C580  1uf,16V  [402]  106.76 72.57 90 bottom
C583  47uF,6.3V  [805]  56.44 65.96 0 bottom
C584  47uF,6.3V  [805]  71.65 83.46 270 bottom
C585  0.01uF  [402]  83.87 64.46 0 top
C586  0.1uf,16V  [201]  94.31 97.28 90 bottom
C587  0.1uf,16V  [201]  97.33 91.11 270 bottom
C588  0.1uf,16V  [201]  100.33 97.28 90 bottom
C589  0.1uf,16V  [201]  103.35 91.11 270 bottom
C590  0.1uf,16V  [201]  106.35 86.97 90 bottom
C591  0.1uf,16V  [201]  103.35 80.72 270 bottom
C592  0.1uf,16V  [201]  100.33 86.92 90 bottom
C593  0.1uf,16V  [201]  97.33 80.8 270 bottom
D1  SK54AFL-TP  [DO221AC]  31.75 70.48 180 top
D2  SK54AFL-TP  [DO221AC]  26.54 84.33 180 top
D3  LTST-C191KFKT  [LED_603]  42.55 65.41 270 top
D4  LTST-C191KFKT  [LED_603]  65.41 2.54 270 top
D5  LTST-C191KFKT  [LED_603]  67.94 2.54 270 top
D6  LTST-C191KFKT  [LED_603]  70.48 2.54 270 top
D7  LTST-C191KFKT  [LED_603]  73.03 2.54 270 top
D8  PESD0603-240  [603]  34.32 2.79 90 bottom
D9  PESD0603-240  [603]  29.24 2.79 90 bottom
D10  PESD0603-240  [603]  47.12 2.79 90 bottom
D11  PESD0603-240  [603]  42.04 2.79 90 bottom
D12  TPD1E05U06  [2XSON]  50.16 94.23 90 top
D13  TPD1E05U06  [2XSON]  51.44 94.23 90 top
D14  TPD1E05U06  [2XSON]  52.7 94.23 90 top
D15  TPD1E05U06  [2XSON]  53.98 94.23 90 top
D16  TPD1E05U06  [2XSON]  55.25 94.23 90 top
D17  TPD1E05U06  [2XSON]  56.52 94.23 90 top
D18  TPD1E05U06  [2XSON]  57.79 94.23 90 top
D19  TPD1E05U06  [2XSON]  59.05 94.23 90 top
D20  TPD2E001DRL  [U_5_DRL]  65.86 9.53 270 top
D21  TPD2E001DRL  [U_5_DRL]  70.31 14.1 270 top
D22  TPD2E001DRL  [U_5_DRL]  74.75 9.53 270 top
D23  TPD2E001DRL  [U_5_DRL]  63.25 12.09 90 top
D24  SK54AFL-TP  [DO221AC]  103 47.5 180 top
D25  TPD2EUSB30ADR  [SOT3_DRT_1P0XP8MM]  89.36 17.27 0 top
D26  TPD2EUSB30ADR  [SOT3_DRT_1P0XP8MM]  86.36 17.27 0 top
D27  TPD2EUSB30ADR  [SOT3_DRT_1P0XP8MM]  84.45 19.43 180 top
D28  TPD2EUSB30ADR  [SOT3_DRT_1P0XP8MM]  108.46 20.45 0 bottom
D29  TPD2EUSB30ADR  [SOT3_DRT_1P0XP8MM]  94.49 17.27 0 bottom
D30  TPD2EUSB30ADR  [SOT3_DRT_1P0XP8MM]  92.84 17.27 0 bottom
D31  TPD2EUSB30ADR  [SOT3_DRT_1P0XP8MM]  100.51 20.45 0 top
D32  TPD2EUSB30ADR  [SOT3_DRT_1P0XP8MM]  77.47 100.58 0 bottom
D33  TPD2EUSB30ADR  [SOT3_DRT_1P0XP8MM]  98.42 20.45 0 top
D34  TPD1E10B06  [2XSON]  111.63 20.32 90 bottom
D35  TPD1E10B06  [2XSON]  82.8 11.56 270 bottom
D36  TPD1E10B06  [2XSON]  101.22 20.45 90 bottom
D37  TPD1E10B06  [2XSON]  82.93 101.6 90 bottom
D38  TPD2EUSB30ADR  [SOT3_DRT_1P0XP8MM]  106.5 20.45 0 top
D40  TPD2EUSB30ADR  [SOT3_DRT_1P0XP8MM]  86.61 6.99 0 bottom
D41  LTST-C191KFKT  [LED_603]  22.86 92.71 270 top
D42  TPD1E10B06  [2XSON]  90.17 6.6 270 bottom
F1  5A_SlowBlow  [FU250_200X400SMD]  27.3 92.46 180 bottom
FB9  150OHM800mA  [805]  58.42 22.35 180 bottom
FL1  DLW21SN900HQ2  [CHOKE4_0805-2]  50.8 91.69 90 top
FL2  DLW21SN900HQ2  [CHOKE4_0805-2]  53.34 91.69 90 top
FL3  DLW21SN900HQ2  [CHOKE4_0805-2]  55.88 91.69 90 top
FL4  DLW21SN900HQ2  [CHOKE4_0805-2]  58.42 91.69 90 top
J1  2POS 1.25MM  [CON2_49LS]  119.38 49.53 0 top
J3  HDR_1x3  [SIP3]  111 97.31 90 top
J4  HDR_1x3  [SIP3]  111 94.77 90 top
J5  HDR_1x1_M_.1,DNI  [SIP2]  75.31 62.87 0 top
J6  HDR_1x3  [SIP3]  111 92.23 90 top
L1  4.7uH  [IND130_208X216]  38.73 69.6 0 top
L2  3.3uH,7A  [IND130_208X216]  36.07 82.55 0 top
L3  1.0uH,4.2A  [IND130_160X175]  71.5 61.59 270 top
L4  1.0uH,4.2A  [IND130_160X175]  66.68 61.59 270 top
L5  1.0uH,4.2A  [IND130_160X175]  61.85 61.59 270 top
L6  1.0uH,2.7A  [IND_1008]  68.33 83.44 90 top
L7  1.0uH,2.7A  [IND_1008]  64.95 83.46 90 top
L8  1.0uH,2.7A  [IND_1008]  61.57 83.49 90 top
L9  1.0uH,4.2A  [IND130_160X175]  57.02 61.59 270 top
L10  FLT_HIFREQ_.47UF  [FLT3SMD_0805-2]  62.24 54.01 270 bottom
L11  FLT_HIFREQ_.47UF  [FLT3SMD_0805-2]  76.58 56.26 90 bottom
L12  FLT_HIFREQ_.47UF  [FLT3SMD_0805-2]  58.42 22.61 180 top
L13  BLM21PG221SN1D  [IND_0805]  53.98 15.62 270 top
L14  BLM21PG221SN1D  [IND_0805]  62.87 20.07 270 top
L15  BLM21PG221SN1D  [IND_0805]  53.98 20.07 270 top
L16  4.7uH  [IND130_208X216]  109.86 47.37 0 top
L17  BLM21PG221SN1D  [IND_0805]  109.86 28.57 0 bottom
L18  BLM21PG221SN1D  [IND_0805]  109.86 24.77 0 bottom
L19  BLM21PG221SN1D  [IND_0805]  109.86 32.38 0 bottom
L20  BLM21PG221SN1D  [IND_0805]  81.03 101.73 270 bottom
L21  FLT_HIFREQ_.47UF  [FLT3SMD_0805-2]  82.04 75.82 270 top
L22  FLT_HIFREQ_.47UF  [FLT3SMD_0805-2]  29.84 55.88 270 bottom
L23  BLM21PG221SN1D  [IND_0805]  27.18 55.88 270 bottom
L24  FLT_HIFREQ_.47UF  [FLT3SMD_0805-2]  74.42 56.26 90 bottom
L25  1.0uH,2.7A  [IND_1008]  56.26 65.91 180 top
L26  1.0uH,2.7A  [IND_1008]  71.58 83.44 90 top
MH1  MOUNT_HOLE  [MTGH250C125D_PL]  16 3.91 0 top
MH2  MOUNT_HOLE  [MTGH250C125D_PL]  121.16 3.91 0 top
MH3  MOUNT_HOLE  [MTGH250C125D_PL]  16 94.31 0 top
MH4  MOUNT_HOLE  [MTGH250C125D_PL]  121.16 94.31 0 top
MH5  MOUNT_HOLE  [MTGH200C102D_PL]  80.26 18.54 0 top
NOREF  -  []  6.35 95.25 0 top
NOREF#2  -  []  126.05 0 0 top
NOREF#3  -  [unnamed#2]  130.81 6.35 0 top
NOREF#4  -  []  11.11 0 0 top
NOREF#5  -  []  -349.76 -265.99 0 top
NOREF#6  -  []  73.66 -80.01 0 top
NOREF#7  -  []  0 0 0 top
NOREF#8  -  []  137.16 0 0 top
NOREF#9  -  [unnamed#2]  6.35 6.35 0 top
NOREF#10  -  []  16 3.91 0 top
NOREF#11  -  []  6.35 6.35 0 top
NOREF#12  -  [unnamed#3]  6.35 12.7 0 top
NOREF#13  -  [unnamed#2]  6.35 95.25 0 top
NOREF#14  -  [unnamed#3]  130.81 95.25 0 top
NOREF#15  -  []  6.35 6.35 0 top
NOREF#16  -  []  121.16 3.91 0 top
NOREF#17  -  []  16 3.91 0 top
NOREF#18  -  [unnamed#3]  130.81 12.7 0 top
NOREF#19  -  []  -349.88 -266.06 0 top
NOREF#20  -  []  16 94.31 0 top
NOREF#21  -  []  0 0 0 top
NOREF#22  -  []  130.81 6.35 0 top
NOREF#23  -  []  0 107.57 0 top
NOREF#24  -  [unnamed#3]  130.81 12.7 180 bottom
NOREF#25  -  [unnamed#3]  130.81 95.25 180 bottom
NOREF#26  -  [unnamed#3]  6.35 12.7 180 bottom
P1  CUI-PJ-080BH  [CNPJ-080BH]  41.28 89.42 180 top
P2  HDR_6x1_M_.1,DNI  [SIP6]  46.99 81.28 0 top
P3  HDR_6x1_M_.1,DNI  [SIP6]  57.15 81.28 0 top
P4  20 Pin JTAG  [HEADER10X2_SMD]  71.12 21.59 0 bottom
P5  RJ-45 Gigabit  [RJ45_2X1_XFRM_LED_NEW]  100.33 78.74 180 top
P6  eSATA  [ESATA-USB_COMBO_RA]  77.47 96.45 90 top
P7  Micro USB-B  [USB5_FCI-10103594]  86.36 4.6 90 bottom
P8  SJ1-3524NG  [JACK5-472X551-SJ1-3524NG]  31.78 4.64 90 top
P9  SJ1-3524NG  [JACK5-472X551-SJ1-3524NG]  44.58 4.64 90 top
P10  HDR_6x1_M_.1  [SIP6]  26.04 45.72 0 top
P11  HDMI-RA-19-TYPEA  [HDMI-SMT-W-FLANGE]  57.79 99.07 180 top
P12  104031-0811  [MOLEX_104031-0811]  69.62 7.54 180 bottom
P13  CONN_USB3.0_A  [USB9RA_2SHIELDED]  82.86 13.43 0 top
P15  GSB311231HR  [USB18RA_4SHIELDED]  100 13.43 0 top
P16  CONN_30x2_0.8  [HDR2X30SMD_FX18-60P-0P8SV]  117.47 69.85 270 bottom
P17  CONN_30x2_0.8  [HDR2X30SMD_FX18-60P-0P8SV]  19.69 27.94 270 bottom
P18  CONN_30x2_0.8  [HDR2X30SMD_FX18-60P-0P8SV]  117.47 27.94 270 bottom
P19  CONN_30x2_0.8  [HDR2X30SMD_FX18-60P-0P8SV]  19.69 69.85 270 bottom
Q3  DMC56404  [SMINI6-F3-B]  64.77 5.77 90 top
Q4  DMC56404  [SMINI6-F3-B]  74.9 6.17 90 top
Q5  NTA4153N  [SC75]  27.18 17.02 0 top
Q6  BSS138  [SC70]  31.24 17.53 0 top
Q7  BSS138/SOT  [SOT-23]  101.85 5.33 0 bottom
Q8  TRN_2N2907  [SOT23-3]  53.98 74.3 0 bottom
Q9  TRN_2N2907  [SOT23-3]  78.61 73.41 180 bottom
R1  .01,1206  [1206]  52.07 73.66 0 top
R2  10.2K,1%  [402]  37.47 63.5 180 top
R3  169K  [402]  28.58 66.29 0 bottom
R4  45.3K  [402]  38.1 65.41 90 top
R5  1.91K  [402]  35.05 64.14 0 bottom
R6  20.5K,1%  [402]  28.58 65.15 0 bottom
R7  .01,1206  [1206]  52.07 81.28 0 top
R8  1K,5%  [402]  43.81 65.41 270 top
R9  169K  [402]  26.16 79.88 0 bottom
R10  10K,1%  [402]  43.18 70.36 180 bottom
R11  20.5K,1%  [402]  26.16 78.61 0 bottom
R12  51.1K  [402]  35.56 80.39 90 bottom
R13  10.2K,1%  [402]  31.88 77.34 180 bottom
R14  3.24K,1%  [402]  29.59 77.34 0 bottom
R15  4.7K  [402]  71.25 18.41 90 top
R16  2.2K,1%  [402]  60.2 77.47 0 bottom
R17  2.2K,1%  [402]  63.63 78.74 270 bottom
R18  2.2K,1%  [402]  61.59 78.74 270 bottom
R19  2.2K,1%  [402]  62.61 78.74 270 bottom
R20  10K,DNI  [402]  60.2 76.45 180 bottom
R21  10K,1%  [402]  60.2 75.44 180 bottom
R22  10K,1%  [402]  60.2 73.41 180 bottom
R23  10K,1%,DNI  [402]  69.09 65.91 90 bottom
R24  10K,1%  [402]  75.31 68.33 0 bottom
R26  10K,1%  [402]  67.06 65.91 270 bottom
R27  10K,1%  [402]  75.31 69.34 0 bottom
R28  10K,1%  [402]  68.07 65.91 90 bottom
R29  0,1%  [402]  73.41 68.71 90 top
R30  0,1%  [402]  73.18 76.45 180 bottom
R31  0,1%,DNI  [402]  90.17 8.64 90 bottom
R32  0,1%  [402]  75.31 67.31 0 bottom
R33  4.7K  [402]  87 81.03 270 top
R34  .01,1206  [1206]  52.07 71.12 0 top
R35  .01,1206  [1206]  52.07 78.74 0 top
R36  .02,1206  [1206]  52.07 76.2 0 top
R37  10K,1%,DNI  [402]  52.07 77.85 0 bottom
R38  DNI,0402  [402]  60.33 24.77 90 bottom
R39  0,1%  [402]  61.21 28.07 270 bottom
R40  DNI,0402  [402]  61.59 24.77 90 bottom
R41  10K,1%  [402]  77.47 64.77 180 bottom
R42  10K,1%  [402]  80.01 65.28 180 bottom
R43  2.2K,1%  [402]  58.55 28.07 270 bottom
R44  10K,1%  [402]  80.01 64.26 180 bottom
R45  DNI,0402  [402]  71.37 78.74 270 bottom
R46  10K,1%  [402]  60.33 28.07 90 bottom
R47  DNI,0402  [402]  59.44 28.07 270 bottom
R48  100K,1%  [402]  56.64 53.59 270 bottom
R49  10K,1%,DNI  [402]  64.64 53.59 90 bottom
R50  10K,1%  [402]  63.75 53.59 90 bottom
R51  10K,1%  [402]  39.88 61.61 180 top
R52  10K,1%  [402]  52.7 10.16 270 top
R53  0,1%  [402]  55.25 10.16 90 top
R54  DNI,0402  [402]  61.59 7.87 90 top
R55  0,1%,DNI  [402]  53.98 10.16 270 top
R56  10K,1%  [402]  52.1 69.49 0 bottom
R57  0,1%  [402]  67.31 49.53 90 bottom
R58  10K,1%  [402]  52.1 66.45 180 bottom
R59  4.7K  [402]  74.3 24.77 270 top
R61  22,5%  [402]  65.66 28.07 270 bottom
R62  4.7K  [402]  74.3 18.41 270 top
R63  22,5%  [402]  66.55 28.07 270 bottom
R64  22,5%  [402]  71.63 24.77 270 top
R66  4.7K  [402]  65.41 18.41 270 top
R68  470,5%  [402]  103.86 100.81 270 bottom
R69  470,5%  [402]  96.72 100.74 90 bottom
R84  22,5%  [402]  84.07 51.56 90 top
R85  22,5%  [402]  83.31 51.56 90 top
R86  22,5%  [402]  82.55 51.56 90 top
R87  22,5%  [402]  81.79 51.56 90 top
R88  22,5%  [402]  81.03 51.56 90 top
R89  22,5%  [402]  80.26 51.56 90 top
R97  470,5%  [402]  101.19 78.69 180 bottom
R98  470,5%  [402]  92.66 78.74 0 bottom
R111  22,5%  [402]  84.07 35.94 90 top
R112  22,5%  [402]  83.31 35.94 90 top
R113  22,5%  [402]  82.55 35.94 90 top
R114  22,5%  [402]  81.79 35.94 90 top
R115  22,5%  [402]  81.03 35.94 90 top
R118  22,5%  [402]  80.26 35.94 90 top
R124  22,5%  [402]  82.93 23.37 0 bottom
R125  22,5%  [402]  82.93 22.48 0 bottom
R126  22,5%  [402]  82.93 24.26 0 bottom
R127  22,5%  [402]  82.93 21.59 0 bottom
R128  22,5%  [402]  82.93 26.04 0 bottom
R129  22,5%  [402]  82.93 25.15 0 bottom
R130  22,5%  [402]  82.93 28.7 0 bottom
R131  22,5%  [402]  82.93 27.81 0 bottom
R132  22,5%  [402]  82.93 26.92 0 bottom
R133  22,5%  [402]  79.88 24.26 0 bottom
R134  22,5%  [402]  79.88 27.81 0 bottom
R135  22,5%  [402]  79.88 26.04 0 bottom
R136  22,5%  [402]  76.96 28.07 270 top
R138  22,5%  [402]  79.88 28.7 0 bottom
R139  22,5%  [402]  79.88 26.92 0 bottom
R140  22,5%  [402]  79.88 29.59 0 bottom
R141  22,5%  [402]  76.07 28.07 270 top
R142  22,5%  [402]  74.3 28.07 270 top
R143  22,5%  [402]  75.18 28.07 270 top
R144  22,5%  [402]  73.41 28.07 270 top
R145  22,5%  [402]  79.88 25.15 0 bottom
R146  22,5%  [402]  71.63 28.07 270 top
R147  22,5%  [402]  72.52 28.07 270 top
R148  22,5%  [402]  69.85 28.07 270 top
R149  22,5%  [402]  79.88 22.48 0 bottom
R150  22,5%  [402]  70.74 28.07 270 top
R152  22,5%  [402]  79.88 23.37 0 bottom
R153  22,5%  [402]  79.88 21.59 0 bottom
R180  10K,1%  [402]  114.3 63.5 180 top
R181  10K,1%  [402]  114.3 64.52 180 top
R182  10K,1%  [402]  120.65 70.61 0 top
R183  10K,1%  [402]  120.65 69.6 0 top
R187  10K,1%  [402]  120.65 68.58 0 top
R188  10K,1%  [402]  120.65 65.53 0 top
R189  10K,1%  [402]  120.65 66.55 0 top
R190  10K,1%  [402]  120.65 60.45 0 top
R191  10K,1%  [402]  120.65 61.47 0 top
R192  10K,1%  [402]  120.65 64.52 0 top
R193  10K,1%  [402]  114.3 62.48 180 top
R194  10K,1%  [402]  114.3 61.47 180 top
R195  10K,1%  [402]  114.3 60.45 180 top
R196  10K,1%  [402]  120.65 63.5 0 top
R197  10K,1%  [402]  120.65 62.48 0 top
R200  10K,1%,DNI  [402]  106.68 39.12 180 bottom
R201  1.87K,1%  [402]  106.68 37.08 0 bottom
R202  1M,1%  [402]  86.36 27.18 180 top
R203  4.99K,1%  [402]  106.68 38.1 0 bottom
R204  4.7K  [402]  95 35.81 90 top
R205  10K,1%  [402]  57.66 28.07 270 bottom
R206  8.25K,1%  [402]  86.36 26.04 0 top
R207  4.7K  [402]  93.22 34.04 90 bottom
R209  4.7K  [402]  91.69 34.04 90 bottom
R210  0,1%  [402]  86.11 8.64 270 bottom
R211  0,1%  [402]  87.12 8.64 270 bottom
R212  2.2K,1%  [402]  72.26 18.41 270 top
R213  2.2K,1%  [402]  67.44 18.41 270 top
R214  10K,1%,DNI  [402]  60.2 72.39 180 bottom
R215  4.7K  [402]  66.68 2.54 270 top
R216  4.7K  [402]  69.22 2.54 270 top
R217  4.7K  [402]  71.75 2.54 270 top
R218  4.7K  [402]  74.3 2.54 270 top
R219  100K,1%  [402]  62.87 5.77 270 top
R220  100K,1%  [402]  66.68 5.77 270 top
R221  100K,1%  [402]  73 6.17 270 top
R222  100K,1%  [402]  76.81 6.17 270 top
R223  22,5%  [402]  64.77 28.07 270 bottom
R224  10,5%  [402]  67.39 32 270 bottom
R225  10,5%  [402]  62.1 28.07 270 bottom
R226  20K,1%  [402]  36.58 14.35 180 bottom
R227  10,5%  [402]  62.99 28.07 270 bottom
R228  20K,1%  [402]  26.92 14.35 0 bottom
R229  10,5%  [402]  63.88 28.07 270 bottom
R230  10,5%  [402]  46.36 12.7 0 bottom
R231  20K,1%  [402]  62.87 16.26 0 top
R232  20K,1%  [402]  62.87 17.53 0 top
R233  10,5%  [402]  42.55 12.7 180 bottom
R234  20K,1%  [402]  40.01 13.72 0 bottom
R235  20K,1%  [402]  48.89 13.72 180 bottom
R236  100K,1%  [402]  28.58 36.83 270 bottom
R237  DNI,0402  [402]  59.31 101.73 270 bottom
R239  10K,1%  [402]  114.3 65.53 180 top
R240  3.24K,1%  [402]  22.86 90.17 90 top
R241  DNI,0402  [402]  60.33 101.73 270 bottom
R242  DNI,0402  [402]  61.34 101.73 90 bottom
R243  4.7K  [402]  90.42 35.81 270 top
R244  0,1%  [402]  61.21 53.59 180 top
R245  4.7K,DNI  [402]  64.01 96.01 90 bottom
R246  4.7K,DNI  [402]  65.02 96.01 90 bottom
R247  10K,1%,DNI  [402]  62.99 96.01 90 bottom
R248  10K,1%,DNI  [402]  66.04 96.01 90 bottom
R249  0,1%  [402]  94.61 49.28 90 bottom
R250  47K,1%  [402]  92.27 44.07 90 bottom
R251  47K,1%  [402]  93.15 44.07 90 bottom
R252  47K,1%  [402]  94.74 38.35 90 bottom
R253  47K,1%  [402]  93.85 38.35 90 bottom
R254  47K,1%  [402]  92.08 38.35 90 bottom
R255  47K,1%  [402]  96.77 40.39 180 bottom
R256  47K,1%  [402]  96.52 38.35 90 bottom
R257  47K,1%  [402]  95.63 38.35 90 bottom
R258  47K,1%  [402]  92.96 38.35 90 bottom
R259  47K,1%  [402]  91.19 38.35 90 bottom
R260  10K,1%  [402]  65.23 11.81 90 top
R261  10K,1%  [402]  66.5 11.81 90 top
R262  10K,1%  [402]  67.77 11.81 90 top
R263  10K,1%  [402]  72.85 11.81 90 top
R264  10K,1%  [402]  74.12 11.81 90 top
R265  10K,1%  [402]  75.39 11.81 90 top
R266  33,5%  [402]  75.39 14.1 270 top
R267  33,5%  [402]  72.85 14.1 270 top
R268  33,5%  [402]  74.12 14.1 270 top
R269  33,5%  [402]  67.77 14.1 270 top
R270  33,5%  [402]  66.5 14.1 270 top
R271  33,5%  [402]  65.23 14.1 270 top
R272  10K,1%  [402]  63.25 10.54 180 top
R273  1K,5%  [402]  54.61 43.18 0 bottom
R274  1K,5%  [402]  54.61 42.16 180 bottom
R275  240,1%  [402]  39.78 40.53 270 bottom
R276  240,1%  [402]  39.38 51.73 270 bottom
R277  240,1%  [402]  39.38 18.13 270 bottom
R278  240,1%  [402]  39.38 29.33 270 bottom
R279  49.9,1%  [402]  40.98 23.73 270 bottom
R280  49.9,1%  [402]  40.18 21.88 90 bottom
R281  49.9,1%  [402]  40.98 21.88 90 bottom
R282  49.9,1%  [402]  40.58 40.53 270 bottom
R283  49.9,1%  [402]  40.18 44.28 90 bottom
R284  49.9,1%  [402]  40.98 44.28 90 bottom
R285  10K,1%  [402]  31.75 18.54 180 top
R286  100K,1%  [402]  25.4 20.45 0 top
R287  10K,1%  [402]  29.72 17.65 0 top
R288  10K,1%  [402]  25.4 21.34 180 top
R289  10,5%  [402]  31.75 22.35 180 top
R290  0,1%  [402]  25.4 23.24 180 top
R291  0,1%  [402]  27.43 23.24 0 top
R292  10.2K,1%  [402]  108.59 41.27 180 top
R293  25.5K,1%  [402]  102.23 29.59 0 top
R294  30K  [402]  99.82 41.27 0 bottom
R295  45.3K  [402]  109.22 43.18 90 top
R296  1.91K  [402]  106.05 41.27 0 bottom
R297  20.5K,1%  [402]  99.82 42.55 0 bottom
R298  63.4K,1%  [402]  102.23 34.67 180 top
R299  0,1%  [402]  84.58 105.41 90 bottom
R300  0,1%  [402]  110.11 20.32 270 bottom
R302  0,1%  [402]  82.04 73.15 270 top
R303  1K,5%  [402]  76.45 76.83 270 bottom
R308  100,5%  [402]  67.31 51.44 270 bottom
R309  100K,1%  [402]  24.89 50.8 270 top
R310  100K,1%,DNI  [402]  26.8 55.24 270 top
R311  DNI,0402  [402]  24.89 48.64 270 top
R312  0,1%  [402]  25.91 55.24 90 top
R313  10K,1%  [402]  27.69 55.24 90 top
R314  27,1%,DNI  [402]  85.63 9.11 180 bottom
R315  27,1%,DNI  [402]  87.6 9.11 0 bottom
R318  1.74K  [402]  66.17 76.83 270 bottom
R319  2K  [402]  66.17 74.93 90 bottom
R320  0,1%,DNI  [402]  95.25 8.51 90 bottom
R321  10K,1%  [402]  56.77 28.07 90 bottom
R322  1.74K,DNI  [402]  70.51 79.1 90 bottom
R323  2K,DNI  [402]  69.62 79.1 270 bottom
R328  1K,5%,DNI  [402]  92.46 34.04 270 bottom
R329  16K  [402]  88.9 35.81 270 top
R330  90.9K,1%  [402]  88.14 35.81 270 top
R331  1M,1812  [1812]  100.38 103.43 90 bottom
R332  0,1%  [402]  25.27 105.41 90 bottom
R333  4.7K  [402]  59.82 53.59 90 bottom
R334  4.7K  [402]  54.61 41.15 180 bottom
R335  10K,1%  [402]  29.72 16.38 0 top
R336  47,1%  [402]  36.18 23.73 270 bottom
R337  47,1%  [402]  36.18 21.88 90 bottom
R338  47,1%  [402]  36.18 18.13 270 bottom
R339  47,1%  [402]  35.38 21.88 90 bottom
R340  47,1%  [402]  39.38 21.88 90 bottom
R341  47,1%  [402]  40.18 27.48 90 bottom
R342  47,1%  [402]  38.58 21.88 90 bottom
R343  47,1%  [402]  39.38 23.73 270 bottom
R344  47,1%  [402]  37.78 27.48 90 bottom
R345  47,1%  [402]  36.98 27.48 90 bottom
R346  47,1%  [402]  36.98 23.73 270 bottom
R347  47,1%  [402]  36.98 18.13 270 bottom
R348  47,1%  [402]  40.18 18.13 270 bottom
R349  47,1%  [402]  40.18 23.73 270 bottom
R350  47,1%  [402]  38.58 27.48 90 bottom
R351  47,1%  [402]  39.38 27.48 90 bottom
R352  47,1%  [402]  38.58 23.73 270 bottom
R353  47,1%  [402]  37.78 18.13 270 bottom
R354  47,1%  [402]  37.78 21.88 90 bottom
R355  47,1%  [402]  37.78 23.73 270 bottom
R356  47,1%  [402]  36.98 21.88 90 bottom
R357  47,1%  [402]  35.38 23.73 270 bottom
R358  47,1%  [402]  36.18 27.48 90 bottom
R359  47,1%  [402]  35.38 18.13 270 bottom
R360  47,1%  [402]  40.18 49.88 90 bottom
R361  47,1%  [402]  40.18 46.13 270 bottom
R362  47,1%  [402]  39.38 49.88 90 bottom
R363  47,1%  [402]  38.58 49.88 90 bottom
R364  47,1%  [402]  37.78 46.13 270 bottom
R365  47,1%  [402]  36.98 44.28 90 bottom
R366  47,1%  [402]  36.98 40.53 270 bottom
R367  47,1%  [402]  36.98 49.88 90 bottom
R368  47,1%  [402]  36.18 46.13 270 bottom
